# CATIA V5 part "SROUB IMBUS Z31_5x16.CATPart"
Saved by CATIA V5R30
Part number: SROUB IMBUS Z31/5x16
Bounding box of the stored display mesh (mm): x -5 to 16, y -4.24 to 4.24, z -4.25 to 4.25
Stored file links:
  C:\Users\ondra\Desktop\PŘÍLOHA P III\CATIA\SROUB IMBUS Z31_5x16.CATPart
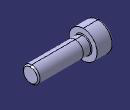
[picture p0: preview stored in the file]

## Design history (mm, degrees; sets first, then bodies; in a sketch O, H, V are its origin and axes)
Set1
  DatumSurface1 to DatumSurface29 "Z31/5x16"
  Join1: Elements (DatumSurface1; DatumSurface2; DatumSurface3; DatumSurface4; DatumSurface5; DatumSurface6; DatumSurface7; DatumSurface8; DatumSurface9; DatumSurface10; DatumSurface11; DatumSurface12; DatumSurface13; DatumSurface14; DatumSurface15; DatumSurface16; DatumSurface17; DatumSurface18; DatumSurface19; DatumSurface20; DatumSurface21; DatumSurface22; DatumSurface23; DatumSurface24; DatumSurface25; DatumSurface26; DatumSurface27; DatumSurface28; DatumSurface29)
Set2 "Geometry Failure"
  Set3 "FaceKO#Z31/5x16#409"
    DatumSurface30 "Sur409_1"
    Circle1 "Crv409_1": stored without definition
    DatumCurve1 "PCrv409_1"
    Circle2 "Crv409_2": stored without definition
    DatumCurve2 "PCrv409_2"
    Circle3 "Crv409_3": stored without definition
    DatumCurve3 "PCrv409_3"
    Circle4 "Crv409_4": stored without definition
    DatumCurve4 "PCrv409_4"
Body1 (main body)
  CloseSurface1: CloseElement Join1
